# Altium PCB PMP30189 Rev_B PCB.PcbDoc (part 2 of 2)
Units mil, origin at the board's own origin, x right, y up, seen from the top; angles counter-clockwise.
Board outline 2450 x 2800 mil, 4 copper layers (Top Layer, Signal Layer 1, Signal Layer 2, Bottom Layer), stack 82.634 mil thick; 88 components, 42 nets, 247 pads, 90 vias.
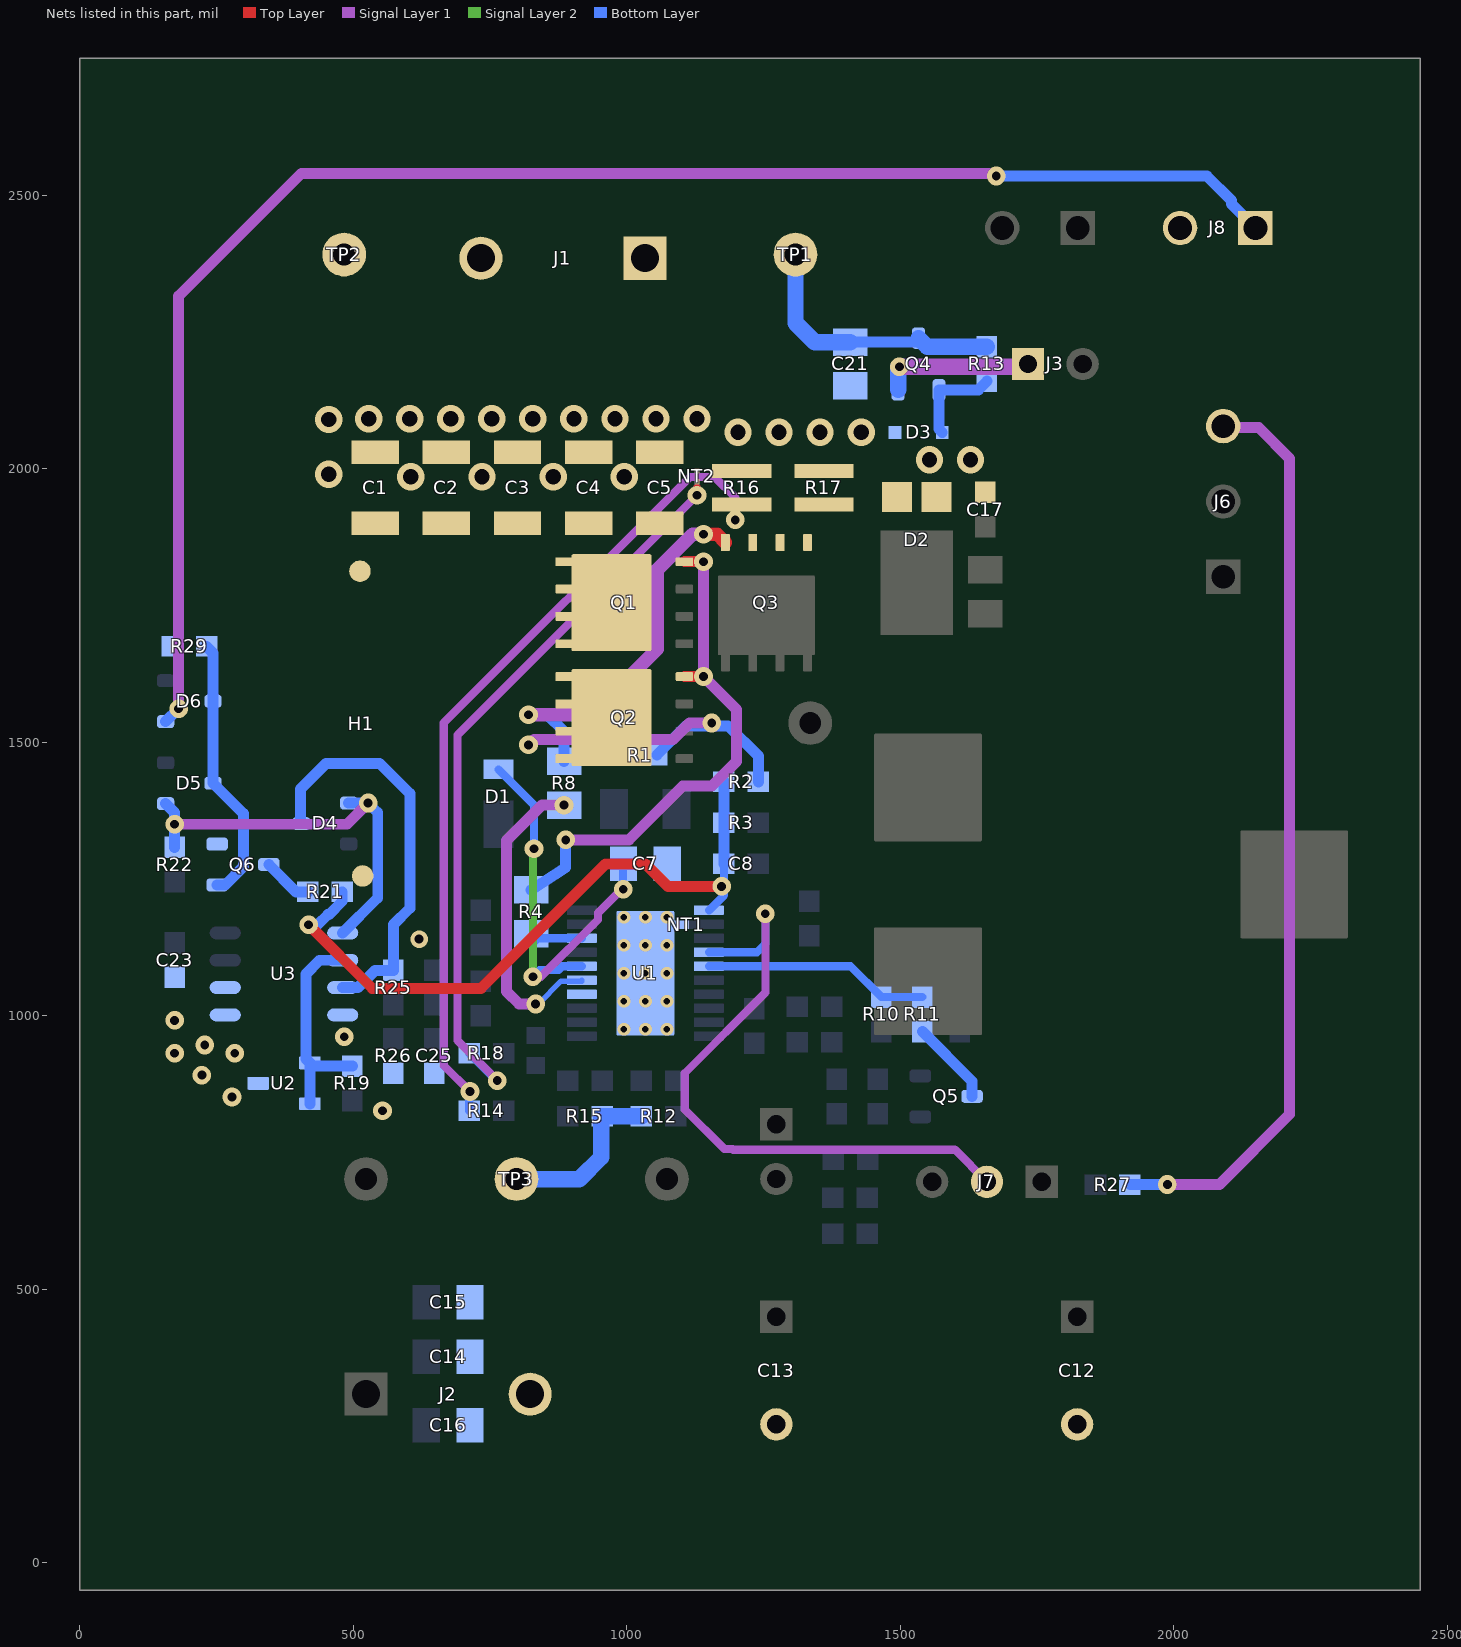
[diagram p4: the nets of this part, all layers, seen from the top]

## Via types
v1: diameter 34, hole 16, Top Layer to Bottom Layer, 51 vias
v2: diameter 50, hole 28, Top Layer to Bottom Layer, 21 vias
v3: diameter 23.62, hole 11.81, Top Layer to Bottom Layer, 9 vias
v4: diameter 23.62, hole 11.81, Top Layer to Bottom Layer, tented both sides, 6 vias
v5: diameter 32, hole 16, Top Layer to Bottom Layer, 2 vias
v6: diameter 34, hole 16, Top Layer to Bottom Layer, tented bottom, 1 vias

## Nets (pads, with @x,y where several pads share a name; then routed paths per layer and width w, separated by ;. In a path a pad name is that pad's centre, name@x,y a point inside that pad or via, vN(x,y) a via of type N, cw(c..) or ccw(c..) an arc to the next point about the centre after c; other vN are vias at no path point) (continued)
NetD3_1: D3.1 Q4.1 R13.1 | length 174.3
  Bottom Layer w20: D3.1@1576.36,2066.38 1570.45,2072.29 Q4.1@1570.45,2144.14 1642.3,2144.14 R13.1@1658.05,2159.89
NetD4_1: D4.1 D5.1 R22.2 U3.1 | length 763.1
  Signal Layer 1 w20: v1(173.05,1350) 488.01,1350 v1(526.79,1388.79)
  Bottom Layer w20: D5.1@156.69,1387.6 173.05,1371.24 v1(173.05,1350) R22.2@173.05,1307.88 ; U3.1@480.33,1151.38 544.5,1215.55 544.5,1371.08 v1(526.79,1388.79) D4.1@491.36,1388.79
NetD4_3: D4.3 R25.2 U3.3 | length 747.6
  Bottom Layer w20: D4.3@404.74,1351.38 403.05,1353.08 403.05,1414.38 450.06,1461.38 548.05,1461.38 603.05,1406.38 603.05,1196.38 573.05,1166.38 R25.2@573.05,1082.88 539.55,1082.88 508.05,1051.38 U3.3@480.33,1051.38
NetD5_3: D5.3 D6.3 Q6.1 R29.2 | length 492.6
  Bottom Layer w20: R29.2@231.5,1675 243.31,1663.19 D6.3@243.31,1575 D5.3@243.31,1425 299.04,1369.27 299.04,1272.43 265.59,1238.98 Q6.1@250.81,1238.98
NetJ3_1: J3.1 Q4.2 | length 280.3
  Signal Layer 1 w30: v1(1498.05,2186.38) 1728.05,2186.38 J3.1@1733.05,2191.38
  Bottom Layer w30: Q4.2@1495.65,2144.14 1495.65,2183.98 v1(1498.05,2186.38)
NetJ6_3: J6.3 R27.1 | length 1689.9
  Signal Layer 1 w20: v1(1988.05,691.38) 2083.05,691.38 2211.48,819.81 2211.48,2018.52 2155,2075 2092.8,2075 J6.3@2090,2077.8
  Bottom Layer w20: R27.1@1919.55,691.38 v1(1988.05,691.38)
NetJ7_2: J7.2 U1.4 | length 1190.5
  Signal Layer 1 w15: v1(1253.05,1186.38) 1253.05,1042.17 1105.68,894.79 1105.68,828.76 1178.05,756.38 1193.05,756.38 1194.35,755.08 1599.35,755.08 J7.2@1658.05,696.38
  Bottom Layer w15: U1.4@1149.82,1115.95 1237.62,1115.95 1253.05,1131.38 v1(1253.05,1186.38)
NetNT2_1: NT2.1 R18.2 | length 1371.6
  Top Layer w15: v1(1128.05,1951.38) v1@1128.05,1965.01
  Signal Layer 1 w15: v1@765.93,884.26 v1(763.05,881.38) 690,954.43 690,1513.33 v1(1128.05,1951.38)
  Bottom Layer w15: R18.2@711.56,931.38 761.56,881.38 v1(763.05,881.38)
NetQ1_4: Q1.4 Q2.4 R4.2 | length 956.8
  Top Layer w20: Q2.4@1105.04,1620 v1(1140,1620) ; Q1.4@1105.04,1830 v1(1140,1830)
  Signal Layer 1 w20: v6(888.05,1321.38) 1003.39,1321.38 1102,1420 1155,1420 1200,1465 1200,1560 v1(1140,1620) v1(1140,1830)
  Bottom Layer w20: R4.2@825,1230 888.05,1271.03 v6(888.05,1321.38)
NetQ3_1: Q3.1 Q3.2 Q3.3 R14.2 R16.2 R17.2 | length 1538.5
  Top Layer w15: v1(1198.05,1906.38) 1198.05,1925.87 R16.2@1208.05,1935.87
  Signal Layer 1 w15: v1(713.05,861.38) 665,909.43 665,1535 1115,1985 1160,1985 1198.05,1946.95 v1(1198.05,1906.38)
  Bottom Layer w15: R14.2@711.56,826.38 711.56,859.89 v1(713.05,861.38)
NetQ3_4: Q3.4 R8.2 | length 720.3
  Top Layer w25: v1(1140,1880) 1165.04,1880 Q3.4@1180,1865.04
  Signal Layer 1 w25: v1(820,1550) 935,1550 1055,1670 1055,1815 1120,1880 v1(1140,1880)
  Bottom Layer w20: v1(820,1550) 855,1550 885,1520 R8.2@885,1465
NetQ5_3: Q5.3 R11.1 | length 156.2
  Bottom Layer w20: R11.1@1540,971.07 1630.93,880.14 Q5.3@1630.93,852.56
NetQ6_3: Q6.3 R21.1 | length 92
  Bottom Layer w20: Q6.3@345.3,1276.38 395.3,1226.38 R21.1@416.56,1226.38
NetR4_1: R4.1 U1.18 | length 93.1
  Bottom Layer w15: R4.1@828.05,1132.92 836.67,1141.54 U1.18@917.54,1141.54
NetR8_1: R8.1 U1.15 | length 573.5
  Signal Layer 1 w20: v1(833.05,1021.38) 803.05,1021.38 780,1044.43 780,1320 845,1385 v1(885,1385)
  Bottom Layer w10: v1(833.05,1021.38) 838.05,1021.38 879.8,1063.14 917.54,1063.14 U1.15@917.54,1064.77
NetR10_2: R10.2 R11.2 U1.5 | length 413.5
  Bottom Layer w15: U1.5@1149.82,1090.36 1408.7,1090.36 R10.2@1465,1034.06 R11.2@1540,1034.06
NetR12_1: R12.1 R15.2 TP3.1 | length 319.2
  Bottom Layer w30: TP3.1@798.05,701.38 913.05,701.38 953.05,741.38 953.05,814.89 R15.2@954.55,816.38 R12.1@1026.56,816.38
NetR19_2: R19.2 U2.1 U2.2 U3.2 | length 398.2
  Bottom Layer w20: U2.2@420.3,838.98 U2.1@420.3,913.79 ; U3.2@480.33,1101.38 438.05,1101.38 413.05,1076.38 413.05,921.03 U2.1@420.3,913.79 ; R19.2@498.05,907.88 426.2,907.88 U2.1@420.3,913.79
ON-OFF: D6.1 J8.1 | length 2894.1
  Signal Layer 1 w20: v1(180.31,1561.22) 180.31,2315.31 405,2540 1670,2540 v1(1675,2535)
  Bottom Layer w20: D6.1@156.69,1537.6 v1(180.31,1561.22) ; v1(1675,2535) 2060,2535 2105,2490 2105,2483.9 J8.1@2148.9,2440
OVV_24V: C8.1 R2.1 R3.2 R21.2 U1.1 | length 1257.1
  Top Layer w20: v1(418.05,1166.38) 534.35,1050.08 733.05,1050.08 960.53,1277.56 1033.68,1277.56 1074.86,1236.38 v1(1173.05,1236.38)
  Bottom Layer w15: U1.1@1149.82,1192.72 1177.18,1220.08 C8.1@1177.18,1277.56
  Bottom Layer w20: v1(418.05,1166.38) 434.78,1166.38 453.05,1184.65 455.02,1184.65 479.55,1209.18 R21.2@479.55,1226.38 ; C8.1@1177.18,1277.56 R3.2@1177.18,1352.56 1177.18,1391.38 R2.1@1177.18,1427.56
SGND: C1.2 C2.2 C3.2 C4.2 C5.2 C7.2 C12.2 C13.2 C14.2 C15.2 C16.2 C17.2 C21.2 C23.2 C25.1 D2.1 D2.2 D3.2 J1.2 J2.2 J8.2 NT1.2 NT2.2 Q6.2 R16.1 R17.1 R26.1 R29.1 TP2.1 U1.14 U1.21@1033.68,1077.56 U2.3 U3.4 U3.5 U3.6
  other v1: 553.05,826.38 278.05,851.38 223.05,891.38 173.05,931.38 283.05,931.38 228.05,946.38 483.05,961.38 173.05,991.38
  other v2: 605,1985 735,1985 865,1985 995,1985 455,1990 1553.05,2016.38 1628.05,2016.38 1203.05,2066.38 1278.05,2066.38 1353.05,2066.38 1428.05,2066.38 455,2090 528.05,2091.38 603.05,2091.38 678.05,2091.38 753.05,2091.38 828.05,2091.38 903.05,2091.38 978.05,2091.38 1053.05,2091.38 1128.05,2091.38
  other v3: 994.31,1026.38 1033.68,1026.38 1073.05,1026.38 994.31,1077.56 1033.68,1077.56 1073.05,1077.56 994.31,1128.75 1033.68,1128.75 1073.05,1128.75
  other v4: 994.31,975.2 1033.68,975.2 1073.05,975.2 994.31,1179.93 1033.68,1179.93 1073.05,1179.93
  other v5: 620,1140
VCC-1: C7.1 D1.2 U1.16 | length 776.9
  Signal Layer 1 w15: v1@843.05,1071.38 947.07,1175.4 947.07,1187.9 985.55,1226.38 993.05,1226.38 v1(993.05,1231.38)
  Signal Layer 2 w15: v1(828.05,1071.38) 828.05,1303.05 v1(830,1305)
  Bottom Layer w15: D1.2@765,1450.2 830,1385.2 v1(830,1305) ; v1(828.05,1071.38) 840.18,1083.51 875.18,1083.51 882.03,1090.36 U1.16@917.54,1090.36 ; v1(993.05,1231.38) 993.05,1276.93 C7.1@993.68,1277.56
VIN: C1.1 C2.1 C3.1 C4.1 C5.1 C21.1 H1.1 H1.2 J1.1 Q1.5 Q1.6 Q1.7 Q1.8 Q1.9@971.77,1755 Q2.5 Q2.6 Q2.7 Q2.8 Q2.9@971.77,1545 Q4.3 R1.1 R2.2 R13.2 TP1.1 | length 1128.5
  Signal Layer 1 w20: v1(820,1495) 829.93,1504.93 1084.07,1504.93 1114.15,1535 v1(1155,1535)
  Bottom Layer w20: R1.1@1054.55,1476.38 1108.16,1530 1185,1530 1240.18,1474.82 R2.2@1240.18,1427.56 ; C21.1@1408.05,2231.38 1525.81,2231.38 Q4.3@1533.05,2238.63
  Bottom Layer w30: TP1.1@1308.05,2391.38 1308.05,2266.38 1343.05,2231.38 C21.1@1408.05,2231.38 ; Q4.3@1533.05,2238.63 1548.8,2222.88 R13.2@1658.05,2222.88
pads on no net: D4.2 D5.2 D6.2 L1.3 Q1.9@939.88,1697.91 Q1.9@939.88,1755 Q1.9@939.88,1812.09 Q1.9@1009.96,1697.91 Q1.9@1009.96,1755 Q1.9@1009.96,1812.09 Q2.9@939.88,1487.91 Q2.9@939.88,1545 Q2.9@939.88,1602.09 Q2.9@1009.96,1487.91 Q2.9@1009.96,1545 Q2.9@1009.96,1602.09 Q3.9@1197.91,1699.88 Q3.9@1197.91,1769.96 Q3.9@1255,1699.88 Q3.9@1255,1769.96 Q3.9@1312.09,1699.88 Q3.9@1312.09,1769.96 U1.7 U1.10 U1.21@1033.68,1077.56 U3.7

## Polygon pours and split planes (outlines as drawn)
GND-1 on Bottom Layer "Bottom Layer-No Net" (solid, pour order 2): 1458.05,1431.38 1433.05,1456.38 1073.05,1456.38 1043.05,1426.38 1043.05,1416.38 1043.05,1261.38 1116.54,1187.9 1120.3,1187.9 1120.3,957.49 1118.05,955.24 1118.05,937.8 1111.63,931.38 983.05,931.38 918.05,931.38 903.05,916.38 903.05,852.84 903.05,787.84 1049.51,641.38 1137.01,553.88 1535.55,553.88 1583.05,601.38 1584.67,858 1584.67,909.65 1583.05,911.27 1583.05,1051.38 1488.05,1146.38 1488.05,1166.38 1488.05,1401.38
SGND on Bottom Layer "S-GND Bottom" (solid, pour order 16): 50.39,2750.89 2343.05,2750.89 2343.05,31.38 2348.05,26.38 49.9,26.38
24V on Bottom Layer "+24V Bottom" (solid, pour order 0): 378.05,551.38 673.05,551.38 673.05,151.38 378.05,151.38
GND-1 on Signal Layer 2 "Bottom Layer-No Net" (solid, pour order 4): 1458.05,1431.38 1433.05,1456.38 1073.05,1456.38 1043.05,1426.38 1043.05,1416.38 1043.05,1261.38 1116.54,1187.9 1120.3,1187.9 1120.3,957.49 1118.05,955.24 1118.05,937.8 1111.63,931.38 918.05,931.38 903.05,916.38 903.05,852.84 903.05,787.84 1049.51,641.38 1368.05,641.38 1584.67,858 1584.67,909.65 1583.05,911.27 1583.05,1051.38 1488.05,1146.38 1488.05,1166.38 1488.05,1401.38
SGND on Signal Layer 2 "S-GND Mid-2" (solid, pour order 14): 50.44,2750.89 2343.05,2750.89 2343.05,31.38 2348.05,26.38 49.96,26.38
SGND on Top Layer "TOP_LAYER_SGND_P020" (solid, remove dead copper, pour order 20): 970,940 1110,940 1170,1000 1170,1180 1150,1200 920,1200 860.19,1140.19 860.19,1014.34 907.3,967.23 942.53,967.23
NetC9_2 on Top Layer "Switch Node" (solid, pour order 6): 1065,1810 1065,1824.92 1466.02,1824.92 1466.59,1824.92 1516.95,1880.93 1698.05,1880.93 1698.05,1586.9 1698.05,1305 1405,1305 1405,1450 1065,1450
NetQ3_1 on Top Layer "Top Layer-No Net" (solid, pour order 8): 1153.05,1966.38 1449.98,1966.38 1449.98,1810 1153.05,1810
SGND on Top Layer "Signal Layer 1-No Net" (solid, pour order 10): 378.05,2161.38 383.05,2161.38 1538.05,2161.38 1688.05,2011.38 1688.05,1926.38 1673.05,1911.38 1662.78,1911.38 1488.05,1911.38 1473.05,1926.38 1473.05,1971.38 1463.05,1981.38 1168.05,1981.38 1088.05,1981.38 1065.55,1958.88 378.05,1958.88
VIN on Top Layer "Vin" (solid, pour order 12): 55,2641.38 2348.05,2641.38 2348.05,2226.38 2303.05,2181.38 368.05,2181.38 343.05,2156.38 343.05,1934.34 1055,1934.34 1055,1323.33 871.1,1139.43 55,1139.43
24V on Top Layer "+24V" (solid, pour order 18): 50,776.96 1310.72,776.96 1355.14,821.38 1355.14,1008.47 1445,1098.33 1445,1235 1521.48,1235 1965,1235 2273.62,926.38 2343.05,856.95 2343.05,901.12 2343.05,28.74 2341.18,26.87 103.05,26.87 50,79.92

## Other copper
Top Layer:
  rectangle net SGND: 1108.05,1981.38 1228.05,2011.38

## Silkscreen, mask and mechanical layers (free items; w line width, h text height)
Top Overlay:
  lines w10: 2250,2600 2335,2600
  text "-" at 700,2715 h80 r180
  text "Vin" at 995,2705 h80 r180
  text "+" at 1065,2695 h80 r270
  text "7V" at 1845,2665 h40 r180
  text "GND" at 2030,2660 h40 r180
  text "Fsw" at 1685,2655 h40 r180
  text "ON/OFF" at 2325,2655 h40 r180
  text "Vin-Trk" at 2375,2025 h40 r90
  text "GND" at 2305,1880 h40 r90
  text "Vout-Trk" at 2380,1620 h40 r90
  text "'.PRJ_Number'.PCB_Rev-" at 2335,170 h108.27 r90
  text "+" at 400,75 h80 r270
  text "-" at 900,75 h80 r180
  text "Vout" at 550,0 h70
Top Solder:
  rectangle: 980,960 1090,1195
M1 Board Outline:
  the board outline again, w10
M2 Board Dimensions:
  rectangle: 0,-275 125,-150
  rectangle: 125,-400 500,-275
  lines w7: 0,-275 1000,-275 ; 125,-400 125,-150 ; 250,-400 250,-150 ; 500,-400 500,-150 ; 750,-400 750,-150 ; 0,-400 1000,-400 1000,-150 0,-150 0,-400
M5 Assembly Top:
  lines w10: -292,-930.17 6308,-930.17 ; -292,-726.83 6310,-726.83 ; -292,-523.5 -292,-1133.5 3713,-1133.5 6310,-1133.5 6310,-523.5 -291.5,-523.5 -291.5,-1133.5 1284,-1133.5 ; 2173,-1133.5 2173,-523.5 ; 3440,-726.83 3440,-523.5 ; 4280,-726.83 4280,-523.5 ; 4902,-1140 4902,-937.17
  text "COMPONENTS MARKED 'DNP' SHOULD NOT BE POPULATED." at 1153.5,-318.5 h60
  text "ASSEMBLY VARIANT:" at 1153,-434 h60
  text ".VariantName" at 2189,-434 h60
  text "BOARD #:" at 2248,-655.67 h60
  text ".PRJ_Number" at 2793.5,-655.67 h60
  text "REV:" at 3638,-655.67 h60
  text ".PCB_Rev" at 3929.5,-655.67 h60
  text "SVN REV:" at 4476,-655.67 h60
  text ".VersionControl_RevNumber" at 4982,-655.67 h60
  text "TID #:" at 2248,-859 h60
  text ".TID" at 2793.5,-859 h60
  text "PLOT NAME =" at -228.5,-1064.34 h60
  text ".plot_File_Name" at 577,-1064.34 h60
  text "GENERATED    :" at 2250,-1064.34 h60
  text ".Print_Date" at 3119.5,-1064.34 h60
  text ".Print_Time" at 3848.5,-1064.34 h60
  text "TEXAS INSTRUMENTS" at 5113,-1064.34 h60
M6 Assembly Bottom:
  lines w10: -292.5,-727.33 6309.5,-727.33 ; -290.5,-930.67 6309.5,-930.67 ; 1115.5,-1140.5 1115.5,-937.67 ; 1737.5,-727.33 1737.5,-524 ; 2577.5,-727.33 2577.5,-524 ; 3844.5,-1134 3844.5,-524 ; 4733.5,-1134 6309,-1134 6309,-524 -292.5,-524 -292.5,-1134 2304.5,-1134 6309.5,-1134 6309.5,-524
  text "COMPONENTS MARKED 'DNP' SHOULD NOT BE POPULATED." at 6102,-318 h60
  text ".VariantName" at 5058,-434 h60
  text "ASSEMBLY VARIANT:" at 6097,-434 h60
  text ".PCB_Rev" at 2088,-656.17 h60
  text "REV:" at 2379.5,-656.17 h60
  text ".PRJ_Number" at 3224,-656.17 h60
  text "BOARD #:" at 3769.5,-656.17 h60
  text "PCB VIEWED FROM BOTTOM SIDE" at 6246,-656.17 h60
  text ".TID" at 3224,-859.5 h60
  text "TID #:" at 3769.5,-859.5 h60
  text "TEXAS INSTRUMENTS" at 904.5,-1064.84 h60
  text ".Print_Time" at 2169,-1064.84 h60
  text ".Print_Date" at 2898,-1064.84 h60
  text "GENERATED    :" at 3767.5,-1064.84 h60
  text ".plot_File_Name" at 5440.5,-1064.84 h60
  text "PLOT NAME =" at 6246,-1064.84 h60
M9 Title Sheet:
  drawing of 57 lines, arcs and shapes, not listed
  text "1" at 739.84,8036.5 h70
  text "2" at 3235.5,8036.5 h70
  text "3" at 5724.84,8036.5 h70
  text "4" at 8231.51,8036.5 h70
  text "5" at 10730.5,8036.5 h70
  text "6" at 13235.5,8036.5 h70
  text "A" at -416.5,6893.5 h70
  text "A" at 14383.5,6893.5 h70
  text "B" at -416.5,4513.5 h70
  text "B" at 14383.5,4513.5 h70
  text "C" at -416.5,2138.5 h70
  text "C" at 14383.5,2138.5 h70
  text "PROJECT TITLE:" at 11343.5,277.5 h45
  text ".PRJ_Title" at 11393.5,144.17 h70
  text "DESIGNED FOR:" at 11343.5,-23.5 h45
  text ".PRJ_Customer" at 11393.5,-163.5 h70
  text "D" at -416.5,-231.5 h70
  text "D" at 14383.5,-231.5 h70
  text "FILE NAME:" at 11343.5,-323.5 h45
  text ".PCB_File_Name_No_Path" at 11393.5,-443.5 h70
  text "Texas Instruments (TI) and/or its licensors do not warrant the accuracy or completeness of this specification" at 6374,-605.34 h45
  text "ENGINEER:" at 11343.5,-613.5 h45
  text "LAYOUT BY:" at 12848.5,-613.5 h45
  text "or any information contained therein. TI and/or its licensors do not warrant that this design will meet" at 6329.01,-718 h45
  text ".PRJ_Engineer" at 11393.5,-768.49 h70
  text ".PCB_Layout" at 12899,-768.49 h70
  text "the specifications, will be suitable for your application or fit for any particular purpose, or will operate in" at 6329.01,-830.67 h45
  text "ALTIUM DESIGNER VERSION:" at 12848.5,-923.5 h45
  text "an implementation. TI and/or its licensors do not warrant that the design is production worthy. You should" at 6329.01,-943.33 h45
  text "completely validate and test your design implementation to confirm the system functionality for your application." at 6374,-1056 h45
  text ".print_Scale" at 11393.5,-1056.83 h70
  text ".Application_BuildNumber" at 12899,-1056.83 h70
  text "1" at 739.84,-1263.5 h70
  text "2" at 3235.5,-1263.5 h70
  text "3" at 5724.84,-1263.5 h70
  text "4" at 8231.51,-1263.5 h70
  text "5" at 10730.5,-1263.5 h70
  text "6" at 13235.5,-1263.5 h70
M10 Fab Notes:
  drawing of 173 lines, arcs and shapes, not listed
  text "DESIGN INFORMATION" at 12378.02,6201 h60
  text "MIN. TRACK WIDTH:" at 11733.46,6021 h60
  text "8" at 12829.7,6021 h60
  text "MIL" at 12984.46,6021 h60
  text "MIN. CLEARANCE:" at 11733.46,5889 h60
  text "0.2" at 12769.7,5889 h60
  text "mm" at 12984.46,5889 h60
  text "MIN. VIA PAD SIZE:" at 11733.46,5757 h60
  text "24" at 12799.71,5757 h60
  text "MIL" at 12984.46,5757 h60
  text "0.05mm (2MIL)" at 12428.46,5615.29 h60
  text "MINIMUM ANNULAR RING" at 11404.23,5611 h60
  text "EXTERNAL" at 13136.46,5611 h60
  text "PER" at 11604.23,5493 h60
  text "IPC-D-275 CLASS 2 LEVEL C" at 11824.23,5493 h60
  text "MIL, HOLES" at 13312.46,5380.71 h60
  text "+/-" at 12920,5380 h60
  text "+/-" at 13774,5380 h60
  text "REGISTRATION TOLERANCES:" at 11404.23,5375 h60
  text "METAL" at 12604,5375 h60
  text "5" at 13180.2,5375 h60
  text "3" at 14013.2,5375 h60
  text "MIL" at 14129.46,5375 h60
  text "+/-" at 13774,5262 h60
  text "HOLE SIZE TOLERANCE (UNLESS OTHERWISE SPECIFIED):" at 11404.23,5257 h60
  text "3" at 14013.2,5257 h60
  text "MIL" at 14129.46,5257 h60
  text "MATERIAL:" at 11329.46,5047.54 h60
  text "FR-4 High Tg" at 12315.9,4907.21 h60
  text "FR-408" at 11750.46,4898.64 h60
  text "OTHER" at 13238.46,4898.64 h60
  text "X" at 12161,4895 h60
  text "62 MIL (1.6mm) +/-10%" at 12070.56,4735.92 h60
  text "THICKNESS:" at 11404.23,4731.64 h60
  text "X" at 11942.4,4731.64 h60
  text "OTHER" at 13355.46,4731.64 h60
  text "TOLERANCE:" at 11404.23,4573.64 h60
  text "X" at 12243.53,4573.64 h60
  text "ANSI IPC-6012 TYPE 3 CLASS 2" at 12430.48,4573.64 h60
  text "OTHER +/-" at 12430.46,4417.64 h60
  text "BOW & TWIST:" at 11404.23,4260.64 h60
  text "X" at 12243.53,4260.64 h60
  text "ANSI IPC-6012 TYPE 3 CLASS 2" at 12430.48,4260.64 h60
  text "OTHER +/-" at 12430.46,4102.13 h60
  text "DRILLING:" at 11329.46,3963.64 h60
  text "REFERENCE:" at 11404.23,3846.64 h60
  text "X" at 12052.46,3846.64 h60
  text "AS SHOWN" at 12239.46,3846.64 h60
  text "X" at 12953.46,3846.64 h60
  text "NC_DRILL FILES" at 13090.46,3846.64 h60
  text "PTH COPPER THICKNESS:" at 11404.23,3688.64 h60
  text "X" at 12534.46,3688.64 h60
  text "20-30 um" at 12671.46,3688.64 h60
  text "OTHER" at 13388.46,3688.64 h60
  text "BOARD FINISH:" at 11329.46,3529.64 h60
  text "SILKSCREEN:" at 11484.68,3411.64 h60
  text "X" at 12433.46,3411.64 h60
  text "TOP" at 12559.46,3411.64 h60
  text "X" at 12943.46,3411.64 h60
  text "BOTTOM" at 13070.46,3411.64 h60
  text "SILKSCREEN COLOR:" at 11484.68,3244.64 h60
  text "X" at 12432.42,3244.64 h60
  text "WHITE" at 12559.46,3244.64 h60
  text "OTHER" at 13070.46,3244.64 h60
  text "X" at 12563.42,3085.44 h60
  text "GREEN" at 12690.46,3085.44 h60
  text "OTHER" at 13308.46,3085.44 h60
  text "SOLDER RESIST COLOR:" at 11484.68,3074.64 h60
  text "X" at 12563.42,2915.44 h60
  text "MATTE" at 12690.46,2915.44 h60
  text "SEMI-GLOSS" at 13308,2914.8 h60
  text "IMMERSION GOLD (ENIG)" at 12390.46,2726.92 h60
  text "ENEPIG" at 13728,2723.64 h60
  text "SURFACE FINISH:" at 11329.46,2722.64 h60
  text "X" at 12203.51,2722.64 h60
  text "IMM. TIN/SILVER OR EQUIV" at 11659,2565.64 h60
  text "OTHER" at 13090.46,2565.64 h60
  text "ARRAY/PANEL:" at 11329.46,2386.64 h60
  text "CUT AND TRIM PER M1 BOARD OUTLINE" at 12390.46,2382.35 h60
  text "N.C. ROUTE" at 12390.46,2230.64 h60
  text "X" at 13069.46,2230.64 h60
  text "V. SCORE" at 13256.46,2230.64 h60
  text "CERTIFICATION:" at 11329.46,2093.64 h60
  text "MATERIALS AND WORKMANSHIP FOR ALL PCBS" at 12054.46,2093.64 h60
  text "TO MEET OR EXCEED THE REQUIREMENTS OF:" at 12054.46,1995.64 h60
  text "X" at 11680.96,1859.13 h60
  text "ANSI IPC-A-600F CLASS ->" at 11819.96,1859.13 h60
  text "X" at 13459.02,1859.13 h60
  text "2" at 13577.96,1859.14 h60
  text "1" at 13262.96,1857.64 h60
  text "3" at 13931.96,1857.64 h60
  text "X" at 12495.02,1699.64 h60
  text "RoHS" at 12631.96,1699.64 h60
  text "OTHER" at 13276.36,1699.64 h60
  text "PER ORDER" at 13673.42,1699.64 h60
  text "ALL BOARDS MUST MEET OR EXCEED UL94-V0 REQUIREMENTS." at 11357,1534 h60
  text "PCB MUST BEAR THE UL94V-0 UL REGISTERED MATERIAL ID NUMBER" at 11357,1414 h60
  text "ADDITIONAL REQUIREMENTS:" at 11329.46,1240.64 h60
  text "MICROSECTION:" at 11404.23,1125.64 h60
  text "YES" at 12309.96,1125.64 h60
  text "REQUIRED" at 13171.46,969.49 h60
  text "BARE BOARD ELEC. TEST:" at 11404.23,966.64 h60
  text "NONE" at 12709.96,966.64 h60
  text "X" at 13044.46,966.64 h60
  text "PER ORDER" at 13763.46,966.64 h60
M11 Gerber Information:
  lines w10: -292,-930.17 6308,-930.17 ; -292,-726.83 6310,-726.83 ; -292,-523.5 -292,-1133.5 3713,-1133.5 6310,-1133.5 6310,-523.5 -291.5,-523.5 -291.5,-1133.5 1284,-1133.5 ; 2173,-1133.5 2173,-523.5 ; 3440,-726.83 3440,-523.5 ; 4280,-726.83 4280,-523.5 ; 4902,-1140 4902,-937.17
  text "BOARD #:" at 2248,-655.67 h60
  text ".PRJ_Number" at 2793.5,-655.67 h60
  text "REV:" at 3638,-655.67 h60
  text ".PCB_Rev" at 3929.5,-655.67 h60
  text "SVN REV:" at 4476,-655.67 h60
  text ".VersionControl_RevNumber" at 4982,-655.67 h60
  text "TID #:" at 2248,-859 h60
  text ".TID" at 2793.5,-859 h60
  text "PLOT NAME =" at -228.5,-1064.34 h60
  text ".plot_File_Name" at 577,-1064.34 h60
  text "GENERATED    :" at 2250,-1064.34 h60
  text ".Print_Date" at 3119.5,-1064.34 h60
  text ".Print_Time" at 3848.5,-1064.34 h60
  text "TEXAS INSTRUMENTS" at 5113,-1064.34 h60
M12 Stackup:
  drawing of 191 lines, arcs and shapes, not listed
  text "Layer" at 9790.34,7830 h60
  text "Name" at 10200.26,7830 h60
  text "Material" at 11130,7830 h60
  text "Thickness" at 11989.77,7830 h60
  text "Constant" at 12639.6,7830 h60
  text "Board Layer Stack" at 13209.46,7830 h60
  text "1" at 9790.34,7710 h60
  text "Top Overlay" at 10200.26,7710 h60
  text "2" at 9790.34,7590 h60
  text "Top Solder" at 10200.26,7590 h60
  text "Solder Resist" at 11130,7590 h60
  text "0.40mil" at 11989.77,7590 h60
  text "3.5" at 12639.6,7590 h60
  text "3" at 9790.34,7470 h60
  text "Top Layer" at 10200.26,7470 h60
  text "Copper" at 11130,7470 h60
  text "1.40mil" at 11989.77,7470 h60
  text "4" at 9790.34,7350 h60
  text "Dielectric1" at 10200.26,7350 h60
  text "FR-4" at 11130,7350 h60
  text "59.20mil" at 11989.77,7350 h60
  text "4.8" at 12639.6,7350 h60
  text "5" at 9790.34,7230 h60
  text "Bottom Layer" at 10200.26,7230 h60
  text "Copper" at 11130,7230 h60
  text "1.40mil" at 11989.77,7230 h60
  text "6" at 9790.34,7110 h60
  text "Bottom Solder" at 10200.26,7110 h60
  text "Solder Resist" at 11130,7110 h60
  text "0.40mil" at 11989.77,7110 h60
  text "3.5" at 12639.6,7110 h60
  text "7" at 9790.34,6990 h60
  text "Bottom Overlay" at 10200.26,6990 h60
Drill Drawing:
  circle w10: c5363.8,3141.62 r27.66
  lines w10: 5336.14,2546.98 5391.46,2546.98 5363.8,2491.67 5336.14,2546.98 ; 5336.14,2616.13 5363.8,2629.96 5391.46,2616.13 5377.63,2643.78 5391.46,2671.44 5363.8,2657.61 5336.14,2671.44 5349.97,2643.78 5336.14,2616.13 ; 5336.14,2740.59 5391.46,2740.59 5391.46,2795.9 5336.14,2795.9 5336.14,2740.59 ; 5336.14,2878.87 5349.97,2878.87 5363.8,2865.04 5377.63,2878.87 5391.46,2878.87 5377.63,2892.7 5391.46,2906.53 5377.63,2906.53 5363.8,2920.36 5349.97,2906.53 5336.14,2906.53 5349.97,2892.7 5336.14,2878.87 ; 5336.14,2989.5 5336.14,3003.33 5349.97,3017.16 5336.14,3030.99 5336.14,3044.82 5349.97,3044.82 5363.8,3030.99 5377.63,3044.82 5391.46,3044.82 5391.46,3030.99 5377.63,3017.16 5391.46,3003.33 5391.46,2989.5 5377.63,2989.5 5363.8,3003.33 5349.97,2989.5 5336.14,2989.5 ; 5336.14,3238.42 5391.46,3238.42 5391.46,3293.74 5336.14,3293.74 5336.14,3238.42 ; 5347.21,3249.48 5380.39,3249.48 5380.39,3282.67 5347.21,3282.67 5347.21,3249.48
  lines w12: 5286,2454.33 8518.76,2454.33 ; 5286,3325.54 8518.76,3325.54 ; 5624.17,2329.87 5624.17,3450 ; 5956.28,2329.87 5956.28,3450 ; 6593.29,2329.87 6593.29,3450 ; 6852.64,2329.87 6852.64,3450 ; 7228.06,2329.87 7228.06,3450 ; 7951.91,2329.87 7951.91,3450 ; 5286,2329.87 8518.76,2329.87 8518.76,3450 5286,3450 5286,2329.87
  text "Symbol" at 5360.68,3362.88 h72
  text "Quantity" at 5661.51,3362.88 h72
  text "Finished Hole Size" at 5993.62,3362.88 h72
  text "Plated" at 6630.62,3362.88 h72
  text "Hole Type" at 6889.98,3362.88 h72
  text "Drill Layer Pair" at 7265.4,3362.88 h72
  text "Hole Tolerance" at 7989.25,3362.88 h72
  text "15" at 5661.51,3238.42 h60
  text "11.81mil (0.300mm)" at 5993.62,3238.42 h60
  text "PTH" at 6630.62,3238.42 h60
  text "Round" at 6889.98,3238.42 h60
  text "Top Layer - Bottom Layer" at 7265.4,3238.42 h60
  text "54" at 5661.51,3113.96 h60
  text "16.00mil (0.406mm)" at 5993.62,3113.96 h60
  text "PTH" at 6630.62,3113.96 h60
  text "Round" at 6889.98,3113.96 h60
  text "Top Layer - Bottom Layer" at 7265.4,3113.96 h60
  text "21" at 5661.51,2989.5 h60
  text "28.00mil (0.711mm)" at 5993.62,2989.5 h60
  text "PTH" at 6630.62,2989.5 h60
  text "Round" at 6889.98,2989.5 h60
  text "Top Layer - Bottom Layer" at 7265.4,2989.5 h60
  text "11" at 5661.51,2865.04 h60
  text "33.46mil (0.850mm)" at 5993.62,2865.04 h60
  text "PTH" at 6630.62,2865.04 h60
  text "Round" at 6889.98,2865.04 h60
  text "Top Layer - Bottom Layer" at 7265.4,2865.04 h60
  text "6" at 5661.51,2740.59 h60
  text "40.00mil (1.016mm)" at 5993.62,2740.59 h60
  text "PTH" at 6630.62,2740.59 h60
  text "Round" at 6889.98,2740.59 h60
  text "Top Layer - Bottom Layer" at 7265.4,2740.59 h60
  text "7" at 5661.51,2616.13 h60
  text "43.31mil (1.100mm)" at 5993.62,2616.13 h60
  text "PTH" at 6630.62,2616.13 h60
  text "Round" at 6889.98,2616.13 h60
  text "Top Layer - Bottom Layer" at 7265.4,2616.13 h60
  text "4" at 5661.51,2491.67 h60
  text "51.18mil (1.300mm)" at 5993.62,2491.67 h60
  text "PTH" at 6630.62,2491.67 h60
  text "Round" at 6889.98,2491.67 h60
  text "Top Layer - Bottom Layer" at 7265.4,2491.67 h60
  text "118 Total" at 5661.51,2367.21 h60
M17 Embedded Cavity:
  text ".Layer_Name" at 577,-858.49 h60
M18 Embedded Assembly:
  text ".Layer_Name" at 577,-858.49 h60
M19 Embedded Keepout:
  text ".Layer_Name" at 577,-858.49 h60

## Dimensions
0,-400 to 1000,-400 on M2 Board Dimensions
0,2750 to 2450,-50 on M2 Board Dimensions
0,0 to 2450,-50 on M2 Board Dimensions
